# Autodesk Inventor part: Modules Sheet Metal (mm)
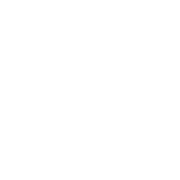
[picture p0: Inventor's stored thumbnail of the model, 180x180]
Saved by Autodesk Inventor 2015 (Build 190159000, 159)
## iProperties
Created: 2014-08
Part Number: Modules Sheet Metal (mm)
Material: Generic
Document SubType Name: Sheet Metal
Designer: Wally
Density: 1 g/cm^3
Sheet Metal Rule: Default
Appearance: Default
Author: Wally
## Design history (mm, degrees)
node "Sketch1"
other parameters: "Thickness" = 0.5, "BendRadius" = 0.5 (= Thickness), "BendReliefWidth" = 0.5 (= Thickness), "BendReliefDepth" = 0.25 (= 0.5 x Thickness), "CornerReliefSize" = 2 (= 4 x Thickness), "SeamGap" = 0.01, "MinimumRemnant" = 1 (= 2 x Thickness), "TransitionRadius" = 0.5 (= BendRadius), "JacobiRadiusSize" = 0.5 (= BendRadius), "GapSize" = 0.5 (= Thickness)
